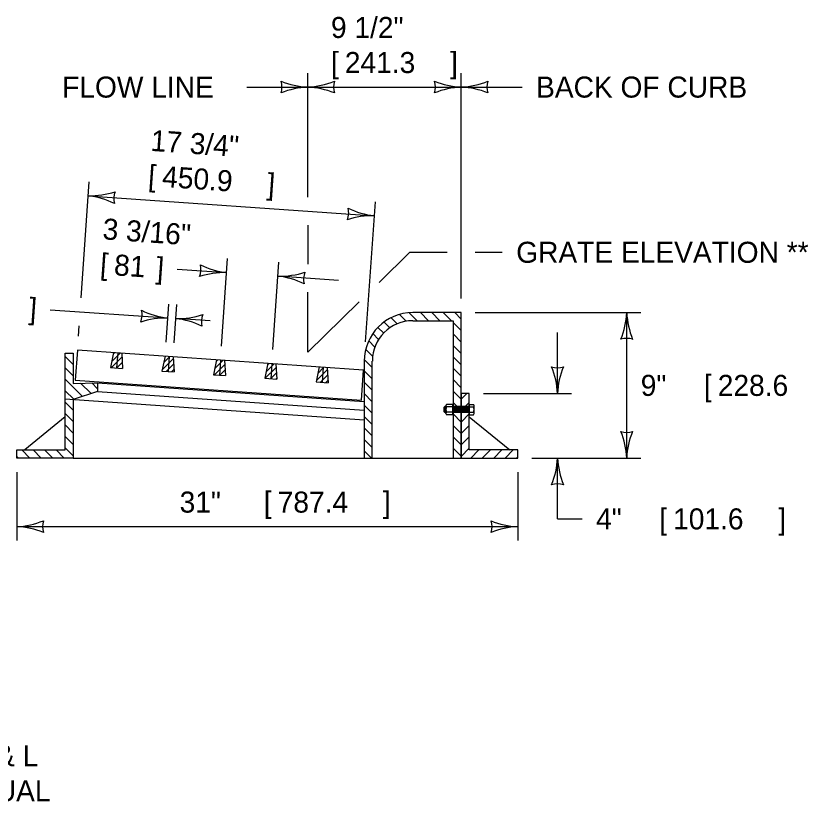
# Model space of a CAD drawing. Extents: x 49991.4 to 50057, y 49987.6 to 50011.4.
# Drawn here: x 50051.224 to 50053.484, y 49994.787 to 49997.044 of the extents above; entities that cross this region are included whole.
import ezdxf

# ---------------------------------------------------------------- set-up
doc = ezdxf.new("R2010")
doc.units = 0
for name, color, linetype in [('Level 1', 7, 'Continuous'), ('Level 2', 7, 'Continuous'), ('Level 3', 7, 'Continuous'), ('Level 4', 7, 'Continuous'), ('Level 5', 7, 'Continuous')]:
    doc.layers.add(name, color=color, linetype=linetype)

msp = doc.modelspace()

# ---------------------------------------------------------------- linework, layer by layer
at = {"layer": 'Level 1'}
for p, q in [((50052.3182, 49996.1923), (50052.3374, 49996.1731)), ((50052.3458, 49996.1973), (50052.3685, 49996.1746)), ((50052.378, 49996.1977), (50052.4011, 49996.1746)), ((50052.4106, 49996.1977), (50052.4337, 49996.1746)), ((50052.4432, 49996.1977), (50052.4663, 49996.1746)), ((50052.4758, 49996.1977), (50052.4945, 49996.179)), ((50052.2744, 49996.1709), (50052.2909, 49996.1544)), ((50052.2947, 49996.1832), (50052.3121, 49996.1658)), ((50052.4714, 49996.1695), (50052.4945, 49996.1464)), ((50052.257, 49996.1557), (50052.2733, 49996.1394)), ((50052.2423, 49996.1378), (50052.2589, 49996.1212)), ((50052.4714, 49996.1369), (50052.4945, 49996.1138)), ((50052.2305, 49996.117), (50052.2481, 49996.0994)), ((50052.4714, 49996.1043), (50052.4945, 49996.0812)), ((50051.5032, 49996.0838), (50051.4945, 49996.0411)), ((50051.498, 49996.0584), (50051.5221, 49996.0825)), ((50051.5022, 49996.0789), (50051.5069, 49996.0836)), ((50051.5262, 49996.0822), (50051.5289, 49996.0387)), ((50052.222, 49996.0929), (50052.2418, 49996.0732)), ((50051.3652, 49996.0729), (50051.3882, 49996.0499)), ((50051.4968, 49996.041), (50051.5269, 49996.071)), ((50051.5121, 49996.0399), (50051.5279, 49996.0557)), ((50051.6498, 49996.0736), (50051.641, 49996.0309)), ((50051.6418, 49996.0347), (50051.6731, 49996.0661)), ((50051.646, 49996.0553), (50051.6634, 49996.0726)), ((50051.6728, 49996.072), (50051.6755, 49996.0285)), ((50051.7963, 49996.0633), (50051.7876, 49996.0206)), ((50051.791, 49996.0374), (50051.8156, 49996.062)), ((50051.7952, 49996.0579), (50051.8004, 49996.0631)), ((50051.8193, 49996.0617), (50051.8221, 49996.0182)), ((50051.9429, 49996.0531), (50051.9341, 49996.0104)), ((50051.9421, 49996.0494), (50051.9457, 49996.0529)), ((50052.218, 49996.0644), (50052.2409, 49996.0414)), ((50052.4714, 49996.0717), (50052.4945, 49996.0486)), ((50051.3652, 49996.0403), (50051.3882, 49996.0173)), ((50051.4945, 49996.0411), (50051.5289, 49996.0387)), ((50051.5273, 49996.0388), (50051.5288, 49996.0404)), ((50051.641, 49996.0309), (50051.6755, 49996.0285)), ((50051.6534, 49996.03), (50051.6741, 49996.0507)), ((50051.6686, 49996.029), (50051.6751, 49996.0354)), ((50051.7904, 49996.0204), (50051.8201, 49996.0501)), ((50051.8056, 49996.0194), (50051.821, 49996.0348)), ((50051.9356, 49996.0103), (50051.9665, 49996.0412)), ((50051.9379, 49996.0289), (50051.9609, 49996.0518)), ((50051.9659, 49996.0515), (50051.9686, 49996.008)), ((50052.0895, 49996.0428), (50052.0807, 49996.0001)), ((50052.0815, 49996.004), (50052.1128, 49996.0353)), ((50052.0857, 49996.0245), (50052.1031, 49996.0419)), ((50052.1125, 49996.0412), (50052.1152, 49995.9977)), ((50052.2179, 49996.0319), (50052.2409, 49996.0088)), ((50052.4714, 49996.0391), (50052.4945, 49996.0161)), ((50051.3652, 49996.0077), (50051.4143, 49995.9586)), ((50051.7876, 49996.0206), (50051.8221, 49996.0182)), ((50051.8208, 49996.0183), (50051.822, 49996.0195)), ((50051.9341, 49996.0104), (50051.9686, 49996.008)), ((50051.9509, 49996.0092), (50051.9675, 49996.0259)), ((50051.9661, 49996.0081), (50051.9685, 49996.0105)), ((50052.0931, 49995.9993), (50052.1138, 49996.02)), ((50051.4091, 49995.9964), (50051.4388, 49995.9668)), ((50051.4411, 49995.997), (50051.4574, 49995.9807)), ((50051.4574, 49995.9972), (50051.4574, 49995.9972)), ((50051.4574, 49995.9972), (50052.2179, 49995.9441)), ((50052.0807, 49996.0001), (50052.1152, 49995.9977)), ((50052.1083, 49995.9982), (50052.1148, 49996.0046)), ((50052.2179, 49995.9993), (50052.2409, 49995.9762)), ((50052.4714, 49996.0065), (50052.4945, 49995.9835)), ((50051.3652, 49995.9751), (50051.3899, 49995.9505)), ((50051.4574, 49995.973), (50052.2179, 49995.9198)), ((50051.5136, 49995.9689), (50051.5136, 49995.9689)), ((50052.2179, 49995.9667), (50052.2409, 49995.9436)), ((50052.4714, 49995.9739), (50052.4945, 49995.9509)), ((50052.4945, 49995.9508), (50052.5108, 49995.9672)), ((50051.3652, 49995.9515), (50052.2179, 49995.8919)), ((50051.3652, 49995.9425), (50051.3882, 49995.9195)), ((50052.4714, 49995.9413), (50052.4945, 49995.9183)), ((50052.4945, 49995.9182), (50052.5175, 49995.9413)), ((50052.2179, 49995.9341), (50052.2409, 49995.911)), ((50052.4452, 49995.9269), (50052.4481, 49995.9297)), ((50052.4452, 49995.9269), (50052.4452, 49995.9153)), ((50052.4466, 49995.9269), (50052.4466, 49995.9153)), ((50052.4481, 49995.9297), (50052.4481, 49995.9125)), ((50052.4509, 49995.9297), (50052.4481, 49995.9297)), ((50052.4495, 49995.9269), (50052.4495, 49995.9153)), ((50052.4509, 49995.9099), (50052.4509, 49995.9323)), ((50052.4707, 49995.9361), (50052.4529, 49995.9361)), ((50052.4707, 49995.9286), (50052.4529, 49995.9286)), ((50052.4707, 49995.9061), (50052.4707, 49995.9361)), ((50052.4714, 49995.9341), (50052.4707, 49995.9341)), ((50052.4714, 49995.9082), (50052.4714, 49995.9341)), ((50052.5175, 49995.9082), (50052.5175, 49995.9341)), ((50052.5175, 49995.9341), (50052.5182, 49995.9341)), ((50052.5182, 49995.9361), (50052.5291, 49995.9361)), ((50052.5182, 49995.9061), (50052.5182, 49995.9361)), ((50052.5182, 49995.9286), (50052.5291, 49995.9286)), ((50052.5311, 49995.9099), (50052.5311, 49995.9323)), ((50051.3652, 49995.9004), (50051.25, 49995.8059)), ((50051.3652, 49995.9099), (50051.3882, 49995.8869)), ((50052.2179, 49995.9015), (50052.2409, 49995.8785)), ((50052.4452, 49995.9153), (50052.4481, 49995.9125)), ((50052.4509, 49995.9125), (50052.4481, 49995.9125)), ((50052.4707, 49995.9136), (50052.4529, 49995.9136)), ((50052.4707, 49995.9061), (50052.4529, 49995.9061)), ((50052.4714, 49995.9082), (50052.4707, 49995.9082)), ((50052.4714, 49995.9087), (50052.4945, 49995.8857)), ((50052.4945, 49995.8856), (50052.5175, 49995.9087)), ((50052.5175, 49995.9082), (50052.5182, 49995.9082)), ((50052.5175, 49995.9004), (50052.6327, 49995.8059)), ((50052.5182, 49995.9136), (50052.5291, 49995.9136)), ((50052.5182, 49995.9061), (50052.5291, 49995.9061)), ((50051.3652, 49995.8774), (50051.3882, 49995.8543)), ((50052.4714, 49995.8761), (50052.4945, 49995.8531)), ((50052.4945, 49995.853), (50052.5175, 49995.8761)), ((50052.2179, 49995.8689), (50052.2409, 49995.8459)), ((50051.3652, 49995.8448), (50051.3882, 49995.8217)), ((50052.2179, 49995.8363), (50052.2409, 49995.8133)), ((50052.4714, 49995.8435), (50052.4945, 49995.8205)), ((50052.4945, 49995.8204), (50052.5175, 49995.8435)), ((50051.2411, 49995.8059), (50051.2642, 49995.7828)), ((50051.2737, 49995.8059), (50051.2968, 49995.7828)), ((50051.3063, 49995.8059), (50051.3294, 49995.7828)), ((50051.3389, 49995.8059), (50051.3619, 49995.7828)), ((50051.3652, 49995.8122), (50051.3882, 49995.7891)), ((50052.4714, 49995.811), (50052.4945, 49995.7879)), ((50052.4945, 49995.7878), (50052.5175, 49995.8109)), ((50052.522, 49995.7828), (50052.5451, 49995.8059)), ((50052.5546, 49995.7828), (50052.5777, 49995.8059)), ((50052.5872, 49995.7828), (50052.6103, 49995.8059)), ((50052.6198, 49995.7828), (50052.6429, 49995.8059)), ((50051.2269, 49995.7875), (50051.2316, 49995.7828)), ((50051.3882, 49995.7828), (50052.4945, 49995.7828)), ((50052.2179, 49995.8037), (50052.2388, 49995.7828)), ((50052.6524, 49995.7828), (50052.6558, 49995.7862))]:
    msp.add_line(p, q, dxfattribs=at)
for points in [[(50052.3562, 49996.1746), (50052.4714, 49996.1746), (50052.4714, 49995.7828), (50052.4945, 49995.7828), (50052.4945, 49996.1977), (50052.3562, 49996.1977)], [(50052.2179, 49996.0594), (50052.2179, 49995.7828), (50052.2409, 49995.7828), (50052.2409, 49996.0594)]]:
    msp.add_lwpolyline(points, dxfattribs=at)
for points in [[(50051.3882, 49995.9499), (50051.3882, 49995.7828), (50051.2269, 49995.7828), (50051.2269, 49995.8059), (50051.3652, 49995.8059), (50051.3652, 49996.0824), (50051.3882, 49996.0824), (50051.3882, 49995.996), (50051.4574, 49995.9972), (50051.4574, 49995.973)], [(50052.2159, 49996.034), (50051.3998, 49996.0911), (50051.3937, 49996.0049), (50052.2099, 49995.9478)], [(50052.5175, 49995.8059), (50052.5175, 49995.9672), (50052.4945, 49995.9672), (50052.4945, 49995.7828), (50052.6558, 49995.7828), (50052.6558, 49995.8059)]]:
    msp.add_lwpolyline(points, close=True, dxfattribs=at)
for centre, radius, start, end in [((50052.3562, 49996.0594), 0.1383, 90, 180), ((50052.3562, 49996.0594), 0.1152, 90, 180), ((50052.4554, 49995.9323), 0.0045, 123.6844, 236.3156), ((50052.4659, 49995.9211), 0.015, 150.0207, 209.9793), ((50052.5266, 49995.9323), 0.0045, 303.6844, 56.3156), ((50052.5161, 49995.9211), 0.015, 330.0207, 29.9793), ((50052.4554, 49995.9099), 0.00449, 123.6376, 236.3624), ((50052.5266, 49995.9099), 0.00449, 303.6376, 56.3624)]:
    msp.add_arc(centre, radius, start, end, dxfattribs=at)
at = {"layer": 'Level 3'}
for p, q in [((50052.0567, 49996.5272), (50052.0567, 49996.881)), ((50052.4945, 49996.2377), (50052.4945, 49996.881)), ((50051.8832, 49996.841), (50052.0567, 49996.841)), ((50052.0567, 49996.841), (50052.4945, 49996.841)), ((50052.4945, 49996.841), (50052.6679, 49996.841)), ((50051.4102, 49996.2397), (50051.4333, 49996.5709)), ((50051.4305, 49996.531), (50052.2467, 49996.4739)), ((50052.2215, 49996.1146), (50052.2495, 49996.5138)), ((50052.0567, 49996.4472), (50052.0567, 49996.3357)), ((50052.2602, 49996.2841), (50052.3479, 49996.3698)), ((50052.3479, 49996.3698), (50052.4545, 49996.3698)), ((50052.5345, 49996.3698), (50052.6113, 49996.3698)), ((50051.8106, 49996.1024), (50051.8281, 49996.3517)), ((50051.9572, 49996.0922), (50051.9746, 49996.3415)), ((50051.6843, 49996.3217), (50051.8253, 49996.3119)), ((50052.1448, 49996.2895), (50051.9718, 49996.3016)), ((50052.0567, 49996.0851), (50052.0567, 49996.2557)), ((50051.6526, 49996.1135), (50051.6602, 49996.2223)), ((50051.6756, 49996.1119), (50051.6832, 49996.2207)), ((50052.0567, 49996.0851), (50052.203, 49996.2282)), ((50051.3218, 49996.2058), (50051.6574, 49996.1824)), ((50052.5345, 49996.1977), (50053.0064, 49996.1977)), ((50052.9664, 49995.7828), (50052.9664, 49996.1977)), ((50051.7782, 49996.1739), (50051.6804, 49996.1808)), ((50051.4026, 49996.131), (50051.4046, 49996.16)), ((50052.769, 49995.9672), (50052.769, 49996.1406)), ((50052.5575, 49995.9672), (50052.8091, 49995.9672)), ((50052.6958, 49995.7828), (50053.0064, 49995.7828)), ((50052.769, 49995.6094), (50052.769, 49995.7828)), ((50051.2269, 49995.7428), (50051.2269, 49995.5473)), ((50052.6558, 49995.7428), (50052.6558, 49995.5473)), ((50052.769, 49995.6094), (50052.839, 49995.6094)), ((50051.2269, 49995.5873), (50052.6558, 49995.5873))]:
    msp.add_line(p, q, dxfattribs=at)
for centre, radius, start, end in [((50052.0658, 49997.0631), 0.2223, 247.456, 267.6395), ((50051.9284, 49996.841), 0.0548, 342.1388, 17.8612), ((50052.0452, 49997.0737), 0.233, 272.8273, 292.0772), ((50052.1849, 49996.841), 0.0548, 162.1388, 197.8612), ((50052.5036, 49997.0631), 0.2223, 247.456, 267.6395), ((50052.3662, 49996.841), 0.0548, 342.1388, 17.8612), ((50052.483, 49997.0737), 0.233, 272.8273, 292.0772), ((50052.6227, 49996.841), 0.0548, 162.1388, 197.8612), ((50052.0681, 49996.6083), 0.233, 92.8273, 112.0772), ((50052.0475, 49996.6188), 0.2223, 67.456, 87.6395), ((50052.5059, 49996.6083), 0.233, 92.8273, 112.0772), ((50052.4853, 49996.6188), 0.2223, 67.456, 87.6395), ((50051.4353, 49996.764), 0.233, 268.8273, 288.0772), ((50051.4059, 49996.3101), 0.2223, 63.456, 83.6395), ((50051.5584, 49996.5221), 0.0548, 158.1388, 193.8612), ((50052.1188, 49996.4829), 0.0548, 338.1388, 13.8612), ((50052.2713, 49996.6949), 0.2223, 243.456, 263.6395), ((50052.2419, 49996.241), 0.233, 88.8273, 108.0772), ((50051.6974, 49996.3208), 0.0548, 338.1388, 13.8612), ((50051.8499, 49996.5328), 0.2223, 243.456, 263.6395), ((50051.8205, 49996.0789), 0.233, 88.8273, 108.0772), ((50051.9766, 49996.5346), 0.233, 268.8273, 288.0772), ((50051.9472, 49996.0807), 0.2223, 63.456, 83.6395), ((50052.0997, 49996.2927), 0.0548, 158.1388, 193.8612), ((50051.5295, 49996.1913), 0.0548, 338.1388, 13.8612), ((50051.682, 49996.4033), 0.2223, 243.456, 263.6395), ((50051.6851, 49996.4137), 0.233, 268.8273, 288.0772), ((50051.8083, 49996.1718), 0.0548, 158.1388, 193.8612), ((50052.7443, 49996.2068), 0.2223, 337.456, 357.6395), ((50053.1991, 49996.2091), 0.233, 182.8273, 202.0772), ((50051.6526, 49995.9494), 0.233, 88.8273, 108.0772), ((50051.6557, 49995.9598), 0.2223, 63.456, 83.6395), ((50052.9664, 49996.0694), 0.0548, 72.1388, 107.8612), ((50052.769, 49996.0954), 0.0548, 252.1388, 287.8612), ((50052.5363, 49995.9557), 0.233, 2.8273, 22.0772), ((50052.9912, 49995.958), 0.2223, 157.456, 177.6395), ((50052.9664, 49995.911), 0.0548, 252.1388, 287.8612), ((50052.7337, 49995.7713), 0.233, 2.8273, 22.0772), ((50053.1885, 49995.7737), 0.2223, 157.456, 177.6395), ((50052.5469, 49995.792), 0.2223, 337.456, 357.6395), ((50053.0018, 49995.7943), 0.233, 182.8273, 202.0772), ((50052.769, 49995.6546), 0.0548, 72.1388, 107.8612), ((50051.2154, 49995.82), 0.233, 272.8273, 292.0772), ((50051.3551, 49995.5873), 0.0548, 162.1388, 197.8612), ((50052.6649, 49995.8094), 0.2223, 247.456, 267.6395), ((50052.5276, 49995.5873), 0.0548, 342.1388, 17.8612), ((50051.2178, 49995.3652), 0.2223, 67.456, 87.6395), ((50052.6673, 49995.3546), 0.233, 92.8273, 112.0772)]:
    msp.add_arc(centre, radius, start, end, dxfattribs=at)
at = {"layer": 'Level 4'}
for p, q in [((50052.5175, 49995.9297), (50052.4714, 49995.9297)), ((50052.4725, 49995.9269), (50052.4725, 49995.9153)), ((50052.474, 49995.9297), (50052.474, 49995.9125)), ((50052.4754, 49995.9269), (50052.4754, 49995.9153)), ((50052.4769, 49995.9297), (50052.4769, 49995.9125)), ((50052.4783, 49995.9269), (50052.4783, 49995.9153)), ((50052.4797, 49995.9297), (50052.4797, 49995.9125)), ((50052.4812, 49995.9269), (50052.4812, 49995.9153)), ((50052.4826, 49995.9297), (50052.4826, 49995.9125)), ((50052.4841, 49995.9269), (50052.4841, 49995.9153)), ((50052.4855, 49995.9297), (50052.4855, 49995.9125)), ((50052.4869, 49995.9269), (50052.4869, 49995.9153)), ((50052.4884, 49995.9297), (50052.4884, 49995.9125)), ((50052.4898, 49995.9269), (50052.4898, 49995.9153)), ((50052.4913, 49995.9297), (50052.4913, 49995.9125)), ((50052.4927, 49995.9269), (50052.4927, 49995.9153)), ((50052.4941, 49995.9297), (50052.4941, 49995.9125)), ((50052.4956, 49995.9269), (50052.4956, 49995.9153)), ((50052.497, 49995.9297), (50052.497, 49995.9125)), ((50052.4985, 49995.9269), (50052.4985, 49995.9153)), ((50052.4999, 49995.9297), (50052.4999, 49995.9125)), ((50052.5013, 49995.9269), (50052.5013, 49995.9153)), ((50052.5028, 49995.9297), (50052.5028, 49995.9125)), ((50052.5042, 49995.9269), (50052.5042, 49995.9153)), ((50052.5057, 49995.9297), (50052.5057, 49995.9125)), ((50052.5071, 49995.9269), (50052.5071, 49995.9153)), ((50052.5085, 49995.9297), (50052.5085, 49995.9125)), ((50052.51, 49995.9269), (50052.51, 49995.9153)), ((50052.5114, 49995.9297), (50052.5114, 49995.9125)), ((50052.5129, 49995.9269), (50052.5129, 49995.9153)), ((50052.5143, 49995.9297), (50052.5143, 49995.9125)), ((50052.5157, 49995.9269), (50052.5157, 49995.9153)), ((50052.5175, 49995.9125), (50052.4714, 49995.9125))]:
    msp.add_line(p, q, dxfattribs=at)
at = {"layer": 'Level 5'}
for p, q in [((50051.5147, 49996.083), (50051.5117, 49996.0399)), ((50051.6613, 49996.0728), (50051.6583, 49996.0297)), ((50051.8078, 49996.0625), (50051.8048, 49996.0194)), ((50051.9544, 49996.0523), (50051.9514, 49996.0092)), ((50052.101, 49996.042), (50052.0979, 49995.9989))]:
    msp.add_line(p, q, dxfattribs=at)

# ---------------------------------------------------------------- texts
at = {"layer": 'Level 2'}
for s, rotation, p in [('9 1/2"', 0, (50052.123, 49996.981)), ('[', 0, (50052.123, 49996.881)), ('241.3', 0, (50052.1626, 49996.881)), (']', 0, (50052.4626, 49996.881)), ('FLOW LINE', 0, (50051.3564, 49996.811)), ('BACK OF CURB', 0, (50052.7079, 49996.811)), ('17 3/4"', 356, (50051.6074, 49996.6591)), ('[', 356, (50051.6004, 49996.5593)), ('450.9', 356, (50051.64, 49996.5566)), (']', 356, (50051.9393, 49996.5356)), ('3 3/16"', 356, (50051.4702, 49996.407)), ('GRATE ELEVATION **', 360, (50052.6513, 49996.3398)), ('[', 356, (50051.4633, 49996.3072)), ('81', 356, (50051.5029, 49996.3044)), (']', 356, (50051.6226, 49996.2961)), (']', 356, (50051.26, 49996.1802)), ('9" ', 360, (50053.0064, 49995.9602)), ('[', 360, (50053.1864, 49995.9602)), ('228.6', 360, (50053.2261, 49995.9602)), ('4" ', 360, (50052.879, 49995.5794)), ('[', 360, (50053.059, 49995.5794)), ('101.6', 360, (50053.0987, 49995.5794)), (']', 360, (50053.3987, 49995.5794))]:
    msp.add_text(s, height=0.06, rotation=rotation, dxfattribs=at).set_placement(p)
for s, p in [('31" ', (50051.6914, 49995.6273)), ('[', (50051.9314, 49995.6273)), ('787.4', (50051.9711, 49995.6273)), (']', (50052.2711, 49995.6273)), ('NOTE: NEENAH FOUNDRY R-3067-L (SHOWN), D & L', (50049.2821, 49994.9037)), ('      FOUNDRY I-3517 TYPE "L" OR APPROVED EQUAL', (50049.2821, 49994.8037))]:
    msp.add_text(s, height=0.06, dxfattribs=at).set_placement(p)

doc.saveas('drawing.dxf')
